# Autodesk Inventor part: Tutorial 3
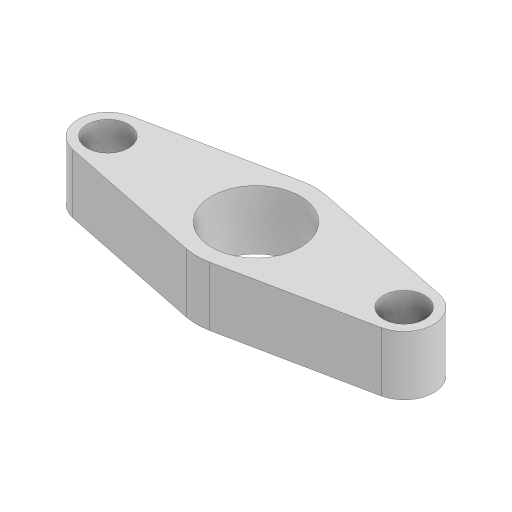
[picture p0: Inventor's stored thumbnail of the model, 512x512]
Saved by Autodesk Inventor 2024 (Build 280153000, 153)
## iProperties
Created: 2021-04
Part Number: Tutorial 3
Material: Generic
Document SubType Name: Modeling
Designer: ASUS Laptop
Density: 1 g/cm^3
Appearance: Default
Author: ASUS Laptop
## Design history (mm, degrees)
sketch "Sketch1"
  geometry: L1 (26, -4.899)-(2, -9.798); L2 (-26, -4.899)-(-2, -9.798); L3 (-26, 4.899)-(-2, 9.798); L4 (26, 4.899)-(2, 9.798); L5 (0, 0)-(-33.69, 0); L6 (0, 0)-(0, -33.352); C1 r 7.5 at (0, 0); C2 r 3.5 at (25, 0); C3 r 3.5 at (-25, 0); A1 r 5 centre (-25, 0) between (-26, 4.899) and (-26, -4.899); A2 r 5 centre (25, 0) between (26, -4.899) and (26, 4.899); A3 r 10 centre (0, 0) between (-2, -9.798) and (2, -9.798); A4 r 10 centre (0, 0) between (2, 9.798) and (-2, 9.798); 1 further point
  constraints: 12 end point, 8 point on circle, 8 tangent, 7 centre point, 4 coincident, 2 equal radius, 2 point on line, 1 horizontal, 1 vertical, 2 other
  dimensions: "d0" = 10 radius of A3; "d1" = 5 radius of A2; "d2" = 50 distance of A1.centre A2.centre; "d3" = 7 diameter of C2; "d4" = 15 diameter of C1
extrude "Extrusion1" new body sketch "Sketch1" distance "d5" = 10; taper "d6" = 0 deg
body "Solid1"
